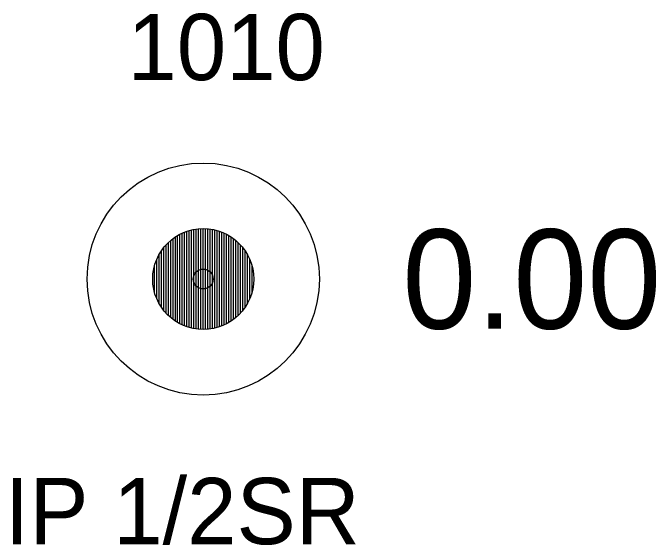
# Model space of a CAD drawing. Extents: x 1393163 to 1398407, y 1072670 to 1074651.
# Drawn here: x 1394549.97 to 1394559.67, y 1073636.42 to 1073644.45 of the extents above; entities that cross this region are included whole.
import ezdxf

# ---------------------------------------------------------------- set-up
doc = ezdxf.new("R2010")
doc.units = 0
for name, color, linetype in [('RD_EX_DV_Prop_txCode', 7, 'Continuous'), ('RD_EX_DV_PropPin', 7, 'Continuous'), ('RD_EX_TX_DV_Prop_ELEV', 7, 'Continuous'), ('RD_SMD_Locator', 7, 'Continuous')]:
    doc.layers.add(name, color=color, linetype=linetype)

msp = doc.modelspace()

# ---------------------------------------------------------------- linework, layer by layer
at = {"layer": 'RD_EX_DV_PropPin'}
for p, q in [((1394552.7364, 1073639.6842), (1394552.7364, 1073641.1916)), ((1394552.7715, 1073639.6801), (1394552.7715, 1073641.1957)), ((1394552.8065, 1073639.6777), (1394552.8065, 1073641.1981)), ((1394552.8415, 1073639.6769), (1394552.8415, 1073641.1989)), ((1394552.8765, 1073639.6777), (1394552.8765, 1073641.1981)), ((1394552.9115, 1073639.6801), (1394552.9115, 1073641.1957)), ((1394552.9465, 1073639.6842), (1394552.9465, 1073641.1916)), ((1394552.4563, 1073639.7815), (1394552.4563, 1073641.0943)), ((1394552.4913, 1073639.7622), (1394552.4913, 1073641.1136)), ((1394552.5264, 1073639.7452), (1394552.5264, 1073641.1306)), ((1394552.5614, 1073639.7303), (1394552.5614, 1073641.1455)), ((1394552.5964, 1073639.7174), (1394552.5964, 1073641.1584)), ((1394552.6314, 1073639.7065), (1394552.6314, 1073641.1693)), ((1394552.6664, 1073639.6973), (1394552.6664, 1073641.1785)), ((1394552.7014, 1073639.6899), (1394552.7014, 1073641.1859)), ((1394552.9815, 1073639.6899), (1394552.9815, 1073641.1859)), ((1394553.0165, 1073639.6973), (1394553.0165, 1073641.1785)), ((1394553.0516, 1073639.7065), (1394553.0516, 1073641.1693)), ((1394553.0866, 1073639.7174), (1394553.0866, 1073641.1584)), ((1394553.1216, 1073639.7303), (1394553.1216, 1073641.1455)), ((1394553.1566, 1073639.7452), (1394553.1566, 1073641.1306)), ((1394553.1916, 1073639.7622), (1394553.1916, 1073641.1136)), ((1394553.2266, 1073639.7815), (1394553.2266, 1073641.0943)), ((1394552.3513, 1073639.8558), (1394552.3513, 1073641.02)), ((1394552.3863, 1073639.828), (1394552.3863, 1073641.0478)), ((1394552.4213, 1073639.8034), (1394552.4213, 1073641.0724)), ((1394553.2616, 1073639.8034), (1394553.2616, 1073641.0724)), ((1394553.2967, 1073639.828), (1394553.2967, 1073641.0478)), ((1394553.3317, 1073639.8558), (1394553.3317, 1073641.02)), ((1394552.2462, 1073639.9637), (1394552.2462, 1073640.9121)), ((1394552.2813, 1073639.9228), (1394552.2813, 1073640.953)), ((1394552.3163, 1073639.8872), (1394552.3163, 1073640.9886)), ((1394553.3667, 1073639.8872), (1394553.3667, 1073640.9886)), ((1394553.4017, 1073639.9228), (1394553.4017, 1073640.953)), ((1394553.4367, 1073639.9637), (1394553.4367, 1073640.9121)), ((1394552.1762, 1073640.0684), (1394552.1762, 1073640.8074)), ((1394552.2112, 1073640.0114), (1394552.2112, 1073640.8644)), ((1394553.4717, 1073640.0114), (1394553.4717, 1073640.8644)), ((1394553.5067, 1073640.0684), (1394553.5067, 1073640.8074)), ((1394552.1412, 1073640.14), (1394552.1412, 1073640.7358)), ((1394553.5418, 1073640.14), (1394553.5418, 1073640.7358)), ((1394552.1062, 1073640.2417), (1394552.1062, 1073640.6341)), ((1394553.5768, 1073640.2417), (1394553.5768, 1073640.6341))]:
    msp.add_line(p, q, dxfattribs=at)
for radius in [1.75, 0.761]:
    msp.add_circle((1394552.8415, 1073640.4379), radius, dxfattribs=at)
at = {"layer": 'RD_SMD_Locator'}
msp.add_circle((1394552.8415, 1073640.4379), 0.15, dxfattribs=at)

# ---------------------------------------------------------------- texts
at = {"layer": 'RD_EX_DV_Prop_txCode'}
for s, p in [('1010', (1394551.6998, 1073643.4379)), ('IP 1/2SR', (1394549.8494, 1073636.4379))]:
    msp.add_text(s, height=1, dxfattribs=at).set_placement(p)
at = {"layer": 'RD_EX_TX_DV_Prop_ELEV'}
msp.add_text('0.00', height=1.5, dxfattribs=at).set_placement((1394555.8415, 1073639.6879))

doc.saveas('drawing.dxf')
